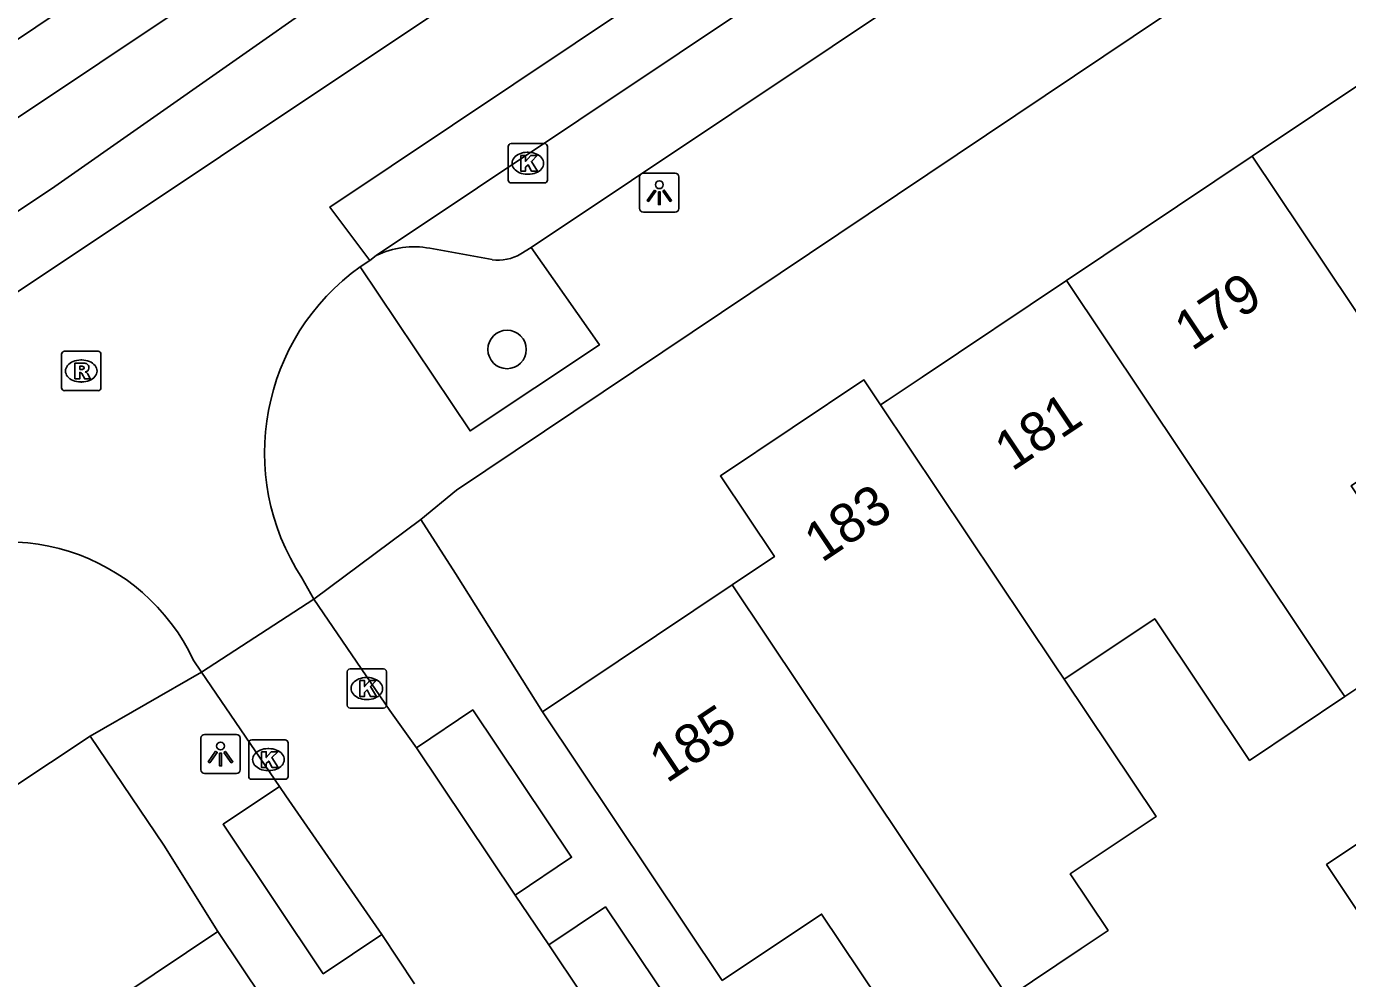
# Model space of a CAD drawing. Extents: x 158352 to 159489, y 383828 to 384597.
# Drawn here: x 158783.7 to 158817.3, y 384168.49 to 384192.7 of the extents above; entities that cross this region are included whole.
import ezdxf

# ---------------------------------------------------------------- set-up
doc = ezdxf.new("R2010")
doc.units = 0
for name, color, linetype in [('IMGEO_Boom', 7, 'Continuous'), ('IMGEO_Kolk', 7, 'Continuous'), ('IMGEO_Lichtpunt', 7, 'Continuous'), ('IMGEO_Pand', 7, 'Continuous'), ('IMGEO_Pand_nummerreeks', 7, 'Continuous'), ('IMGEO_Parkeervlak_open', 7, 'Continuous'), ('IMGEO_Rijbaan_lokaal_gesloten', 7, 'Continuous'), ('IMGEO_Rijbaan_lokaal_open', 7, 'Continuous'), ('IMGEO_Rioolput', 7, 'Continuous'), ('IMGEO_Voetpad_open', 7, 'Continuous')]:
    doc.layers.add(name, color=color, linetype=linetype)

msp = doc.modelspace()

# ---------------------------------------------------------------- linework, layer by layer
at = {"layer": 'IMGEO_Boom'}
msp.add_circle((158795.924, 384184.49), 0.489, dxfattribs=at)
at = {"layer": 'IMGEO_Kolk'}
for p, q in [((158795.951, 384188.799), (158795.951, 384189.651)), ((158796.026, 384189.725), (158796.878, 384189.725)), ((158796.952, 384189.651), (158796.952, 384188.799)), ((158796.439, 384189.505), (158796.464, 384189.505)), ((158796.462, 384188.945), (158796.437, 384188.945)), ((158796.878, 384188.725), (158796.026, 384188.725)), ((158791.857, 384175.443), (158791.857, 384176.295)), ((158791.932, 384176.369), (158792.784, 384176.369)), ((158792.858, 384176.295), (158792.858, 384175.443)), ((158792.345, 384176.149), (158792.37, 384176.149)), ((158792.368, 384175.589), (158792.343, 384175.589)), ((158792.784, 384175.369), (158791.932, 384175.369)), ((158789.429, 384174.562), (158790.281, 384174.562)), ((158789.354, 384173.636), (158789.354, 384174.488)), ((158789.842, 384174.342), (158789.867, 384174.342)), ((158790.355, 384174.488), (158790.355, 384173.636)), ((158790.281, 384173.562), (158789.429, 384173.562)), ((158789.865, 384173.782), (158789.84, 384173.782))]:
    msp.add_line(p, q, dxfattribs=at)
for points in [[(158795.951, 384188.799), (158795.951, 384189.651)], [(158796.026, 384189.725), (158796.878, 384189.725)], [(158796.952, 384189.651), (158796.952, 384188.799)], [(158796.272, 384189.425), (158796.395, 384189.425), (158796.395, 384189.274), (158796.525, 384189.425), (158796.689, 384189.425), (158796.543, 384189.274), (158796.696, 384189.025), (158796.544, 384189.025), (158796.459, 384189.189), (158796.395, 384189.122), (158796.395, 384189.025), (158796.272, 384189.025), (158796.272, 384189.425)], [(158796.878, 384188.725), (158796.026, 384188.725)], [(158791.857, 384175.443), (158791.857, 384176.295)], [(158791.932, 384176.369), (158792.784, 384176.369)], [(158792.858, 384176.295), (158792.858, 384175.443)], [(158792.178, 384176.069), (158792.301, 384176.069), (158792.301, 384175.918), (158792.431, 384176.069), (158792.595, 384176.069), (158792.449, 384175.918), (158792.602, 384175.669), (158792.45, 384175.669), (158792.365, 384175.833), (158792.301, 384175.766), (158792.301, 384175.669), (158792.178, 384175.669), (158792.178, 384176.069)], [(158792.784, 384175.369), (158791.932, 384175.369)], [(158789.429, 384174.562), (158790.281, 384174.562)], [(158789.354, 384173.636), (158789.354, 384174.488)], [(158789.675, 384174.262), (158789.798, 384174.262), (158789.798, 384174.111), (158789.928, 384174.262), (158790.092, 384174.262), (158789.946, 384174.111), (158790.099, 384173.862), (158789.947, 384173.862), (158789.862, 384174.026), (158789.798, 384173.959), (158789.798, 384173.862), (158789.675, 384173.862), (158789.675, 384174.262)], [(158790.355, 384174.488), (158790.355, 384173.636)], [(158790.281, 384173.562), (158789.429, 384173.562)]]:
    msp.add_lwpolyline(points, dxfattribs=at)
for centre, start, end in [((158796.028, 384189.649), 91.552, 178.448), ((158796.028, 384189.649), 91.552, 178.448), ((158796.876, 384189.649), 1.552, 88.448), ((158796.876, 384189.649), 1.552, 88.448), ((158796.028, 384188.801), 181.552, 268.448), ((158796.028, 384188.801), 181.552, 268.448), ((158796.876, 384188.801), 271.552, 358.448), ((158796.876, 384188.801), 271.552, 358.448), ((158791.934, 384176.293), 91.552, 178.448), ((158791.934, 384176.293), 91.552, 178.448), ((158792.782, 384176.293), 1.552, 88.448), ((158792.782, 384176.293), 1.552, 88.448), ((158791.934, 384175.445), 181.552, 268.448), ((158791.934, 384175.445), 181.552, 268.448), ((158792.782, 384175.445), 271.552, 358.448), ((158792.782, 384175.445), 271.552, 358.448), ((158789.431, 384174.486), 91.552, 178.448), ((158789.431, 384174.486), 91.552, 178.448), ((158790.279, 384174.486), 1.552, 88.448), ((158790.279, 384174.486), 1.552, 88.448), ((158789.431, 384173.638), 181.552, 268.448), ((158789.431, 384173.638), 181.552, 268.448), ((158790.279, 384173.638), 271.552, 358.448), ((158790.279, 384173.638), 271.552, 358.448)]:
    msp.add_arc(centre, 0.0765, start, end, dxfattribs=at)
for centre, major_axis, ratio, start_param, end_param in [((158796.438, 384189.225), (-0.387, 0.002), 0.722429, 4.712389, 7.853982), ((158796.463, 384189.225), (-0.39, 0.002), 0.717154, 1.570796, 4.712389), ((158792.344, 384175.869), (-0.387, 0.002), 0.722429, 4.712389, 7.853982), ((158792.369, 384175.869), (-0.39, 0.002), 0.717154, 1.570796, 4.712389), ((158789.841, 384174.062), (-0.387, 0.002), 0.722429, 4.712389, 7.853982), ((158789.866, 384174.062), (-0.39, 0.002), 0.717154, 1.570796, 4.712389)]:
    msp.add_ellipse(centre, major_axis=major_axis, ratio=ratio, start_param=start_param, end_param=end_param, dxfattribs=at)
at = {"layer": 'IMGEO_Lichtpunt'}
for p, q in [((158800.198, 384188.976), (158799.39, 384188.976)), ((158800.198, 384188.976), (158799.39, 384188.976)), ((158799.296, 384188.881), (158799.296, 384188.074)), ((158799.296, 384188.881), (158799.296, 384188.074)), ((158800.292, 384188.074), (158800.292, 384188.881)), ((158800.292, 384188.074), (158800.292, 384188.881)), ((158799.39, 384187.98), (158800.198, 384187.98)), ((158799.39, 384187.98), (158800.198, 384187.98)), ((158788.139, 384174.608), (158788.139, 384173.801)), ((158788.139, 384174.608), (158788.139, 384173.801)), ((158789.041, 384174.703), (158788.233, 384174.703)), ((158789.041, 384174.703), (158788.233, 384174.703)), ((158789.135, 384173.801), (158789.135, 384174.608)), ((158789.135, 384173.801), (158789.135, 384174.608)), ((158788.233, 384173.707), (158789.041, 384173.707)), ((158788.233, 384173.707), (158789.041, 384173.707))]:
    msp.add_line(p, q, dxfattribs=at)
for points in [[(158799.67, 384188.545), (158799.709, 384188.517), (158799.521, 384188.255), (158799.483, 384188.282), (158799.67, 384188.545)], [(158799.772, 384188.497), (158799.819, 384188.497), (158799.819, 384188.175), (158799.772, 384188.175), (158799.772, 384188.497)], [(158799.882, 384188.517), (158799.92, 384188.544), (158800.107, 384188.282), (158800.068, 384188.254), (158799.882, 384188.517)], [(158788.513, 384174.272), (158788.552, 384174.244), (158788.364, 384173.982), (158788.326, 384174.009), (158788.513, 384174.272)], [(158788.615, 384174.224), (158788.662, 384174.224), (158788.662, 384173.902), (158788.615, 384173.902), (158788.615, 384174.224)], [(158788.725, 384174.244), (158788.763, 384174.271), (158788.95, 384174.009), (158788.911, 384173.981), (158788.725, 384174.244)]]:
    msp.add_lwpolyline(points, dxfattribs=at)
for centre in [(158799.795, 384188.679), (158788.638, 384174.406)]:
    msp.add_circle(centre, 0.0994, dxfattribs=at)
for centre, start, end in [((158799.39, 384188.881), 90, 180), ((158799.39, 384188.881), 90, 180), ((158800.198, 384188.881), 0, 90), ((158800.198, 384188.881), 0, 90), ((158799.39, 384188.074), 180, 270), ((158799.39, 384188.074), 180, 270), ((158800.198, 384188.074), 270, 0), ((158800.198, 384188.074), 270, 360), ((158788.233, 384174.608), 90, 180), ((158788.233, 384174.608), 90, 180), ((158789.041, 384174.608), 0, 90), ((158789.041, 384174.608), 0, 90), ((158788.233, 384173.801), 180, 270), ((158788.233, 384173.801), 180, 270), ((158789.041, 384173.801), 270, 0), ((158789.041, 384173.801), 270, 360)]:
    msp.add_arc(centre, 0.0946, start, end, dxfattribs=at)
at = {"layer": 'IMGEO_Pand'}
for points in [[(158819.601, 384192.568), (158814.875, 384189.406)], [(158810.15, 384186.245), (158814.875, 384189.406)], [(158814.875, 384189.406), (158819.306, 384182.782), (158819.527, 384182.452)], [(158810.15, 384186.245), (158806.481, 384183.79), (158805.587, 384183.192), (158805.424, 384183.083)], [(158817.228, 384175.663), (158817.111, 384175.837), (158810.15, 384186.245)], [(158805.424, 384183.083), (158805, 384183.716), (158801.35, 384181.275), (158802.724, 384179.222), (158801.648, 384178.502)], [(158810.093, 384176.104), (158809.849, 384176.468), (158805.424, 384183.083)], [(158817.228, 384175.663), (158819.819, 384177.396), (158817.392, 384181.024), (158819.527, 384182.452)], [(158801.648, 384178.502), (158796.822, 384175.274)], [(158801.648, 384178.502), (158808.664, 384168.014)], [(158810.093, 384176.104), (158812.397, 384177.645), (158814.806, 384174.043), (158817.228, 384175.663)], [(158808.664, 384168.014), (158810.525, 384169.26), (158811.208, 384169.717), (158810.247, 384171.154), (158812.428, 384172.613), (158810.093, 384176.104)], [(158796.822, 384175.274), (158801.394, 384168.443)], [(158820.863, 384170.227), (158818.572, 384168.693), (158816.764, 384171.393), (158819.057, 384172.928)], [(158801.394, 384168.443), (158803.921, 384170.134), (158806.369, 384166.478), (158808.664, 384168.014)], [(158788.571, 384169.689), (158783.739, 384166.456)], [(158795.589, 384159.199), (158793.143, 384162.855), (158788.571, 384169.689)]]:
    msp.add_lwpolyline(points, dxfattribs=at)
at = {"layer": 'IMGEO_Parkeervlak_open'}
for points in [[(158795.542, 384186.774), (158793.959, 384187.064)], [(158796.537, 384187.087), (158796.27, 384186.921)]]:
    msp.add_lwpolyline(points, dxfattribs=at)
for centre, radius, start, end in [((158793.556, 384184.943), 2.159, 79.2499, 116.3256), ((158795.705, 384187.842), 1.081, 261.3205, 301.5112)]:
    msp.add_arc(centre, radius, start, end, dxfattribs=at)
at = {"layer": 'IMGEO_Rijbaan_lokaal_gesloten'}
for points in [[(158792.434, 384186.755), (158791.418, 384188.112), (158833.556, 384216.278)], [(158792.599, 384186.878), (158833.75, 384214.368)], [(158803.043, 384201.515), (158804.21, 384199.782), (158801.066, 384197.693), (158757.561, 384168.674)], [(158756.613, 384170.048), (158784.422, 384188.633), (158795.826, 384196.626), (158802.34, 384200.987)], [(158792.434, 384186.755), (158792.599, 384186.878)]]:
    msp.add_lwpolyline(points, dxfattribs=at)
at = {"layer": 'IMGEO_Rijbaan_lokaal_open'}
for points in [[(158792.192, 384186.594), (158792.434, 384186.755)], [(158791.011, 384178.139), (158790.706, 384178.683)], [(158788.151, 384176.288), (158791.011, 384178.139)], [(158791.011, 384178.139), (158792.942, 384175.309), (158793.621, 384174.365)], [(158788.151, 384176.288), (158787.941, 384176.601)], [(158790.136, 384173.378), (158788.151, 384176.288)], [(158796.133, 384170.618), (158793.621, 384174.365)], [(158790.136, 384173.378), (158790.298, 384173.141), (158792.736, 384169.614)], [(158796.133, 384170.618), (158796.984, 384169.349)], [(158793.574, 384168.357), (158792.736, 384169.614)], [(158799.507, 384165.586), (158796.984, 384169.349)]]:
    msp.add_lwpolyline(points, dxfattribs=at)
for centre, radius, start, end in [((158795.563, 384181.866), 5.807, 125.488, 213.2351), ((158783.223, 384174.381), 5.214, 25.2002, 119.7651)]:
    msp.add_arc(centre, radius, start, end, dxfattribs=at)
at = {"layer": 'IMGEO_Rioolput'}
for p, q in [((158784.595, 384183.517), (158784.595, 384184.369)), ((158784.67, 384184.443), (158785.522, 384184.443)), ((158785.596, 384184.369), (158785.596, 384183.517)), ((158785.083, 384184.223), (158785.108, 384184.223)), ((158785.106, 384183.663), (158785.081, 384183.663)), ((158785.522, 384183.443), (158784.67, 384183.443))]:
    msp.add_line(p, q, dxfattribs=at)
for points in [[(158784.595, 384183.517), (158784.595, 384184.369)], [(158784.67, 384184.443), (158785.522, 384184.443)], [(158785.596, 384184.369), (158785.596, 384183.517)], [(158785.184, 384184.141), (158784.932, 384184.143), (158784.932, 384183.743)], [(158784.932, 384183.743), (158785.056, 384183.743), (158785.056, 384183.905), (158785.067, 384183.905)], [(158785.11, 384184.062), (158785.056, 384184.062), (158785.056, 384183.981)], [(158785.056, 384183.981), (158785.108, 384183.981)], [(158785.114, 384183.876), (158785.185, 384183.743), (158785.325, 384183.743), (158785.26, 384183.869)], [(158785.522, 384183.443), (158784.67, 384183.443)]]:
    msp.add_lwpolyline(points, dxfattribs=at)
for centre, radius, start, end in [((158784.672, 384184.367), 0.0765, 91.552, 178.448), ((158784.672, 384184.367), 0.0765, 91.552, 178.448), ((158785.52, 384184.367), 0.0765, 1.552, 88.448), ((158785.52, 384184.367), 0.0765, 1.552, 88.448), ((158785.066, 384183.852), 0.0533, 26.0293, 88.6989), ((158785.092, 384184.17), 0.19, 274.7715, 282.9687), ((158785.116, 384183.966), 0.0964, 77.0061, 93.1865), ((158785.13, 384184.023), 0.0378, 276.6634, 79.6772), ((158785.183, 384184.031), 0.109, 350.3612, 89.416), ((158785.181, 384184.031), 0.112, 277.5842, 350.9817), ((158785.165, 384183.816), 0.108, 29.5134, 73.7905), ((158784.672, 384183.519), 0.0765, 181.552, 268.448), ((158784.672, 384183.519), 0.0765, 181.552, 268.448), ((158785.52, 384183.519), 0.0765, 271.552, 358.448), ((158785.52, 384183.519), 0.0765, 271.552, 358.448)]:
    msp.add_arc(centre, radius, start, end, dxfattribs=at)
for centre, major_axis, ratio, start_param, end_param in [((158785.082, 384183.943), (-0.387, 0.002), 0.722429, 4.712389, 7.853982), ((158785.107, 384183.943), (-0.39, 0.002), 0.717154, 1.570796, 4.712389)]:
    msp.add_ellipse(centre, major_axis=major_axis, ratio=ratio, start_param=start_param, end_param=end_param, dxfattribs=at)
at = {"layer": 'IMGEO_Voetpad_open'}
for points in [[(158841.042, 384212.024), (158794.638, 384180.916), (158793.73, 384180.171)], [(158752.1, 384171.43), (158802.113, 384204.829)], [(158799.425, 384201.034), (158757.838, 384173.287)], [(158809.298, 384195.612), (158796.537, 384187.087)], [(158796.537, 384187.087), (158798.271, 384184.606), (158794.984, 384182.421), (158792.192, 384186.594)], [(158791.011, 384178.139), (158793.73, 384180.171)], [(158793.73, 384180.171), (158794.611, 384178.792), (158796.822, 384175.274)], [(158785.32, 384174.656), (158788.151, 384176.288)], [(158793.621, 384174.365), (158795.052, 384175.324), (158797.564, 384171.577), (158796.133, 384170.618)], [(158747.356, 384149.809), (158754.637, 384154.044), (158777.222, 384169.281), (158785.32, 384174.656)], [(158785.32, 384174.656), (158787.198, 384171.886), (158788.571, 384169.689)], [(158792.736, 384169.614), (158791.248, 384168.616), (158788.701, 384172.416), (158790.136, 384173.378)], [(158796.984, 384169.349), (158798.427, 384170.317), (158800.95, 384166.554), (158799.507, 384165.586)]]:
    msp.add_lwpolyline(points, dxfattribs=at)

# ---------------------------------------------------------------- texts
at = {"layer": 'IMGEO_Pand_nummerreeks'}
for s, rotation, p in [('179', 33.7834, (158813.343, 384184.435)), ('181', 33.7816, (158808.77, 384181.375)), ('183', 33.7529, (158803.928, 384179.053)), ('185', 33.764, (158799.988, 384173.446))]:
    msp.add_text(s, height=1, rotation=rotation, dxfattribs=at).set_placement(p)

doc.saveas('drawing.dxf')
